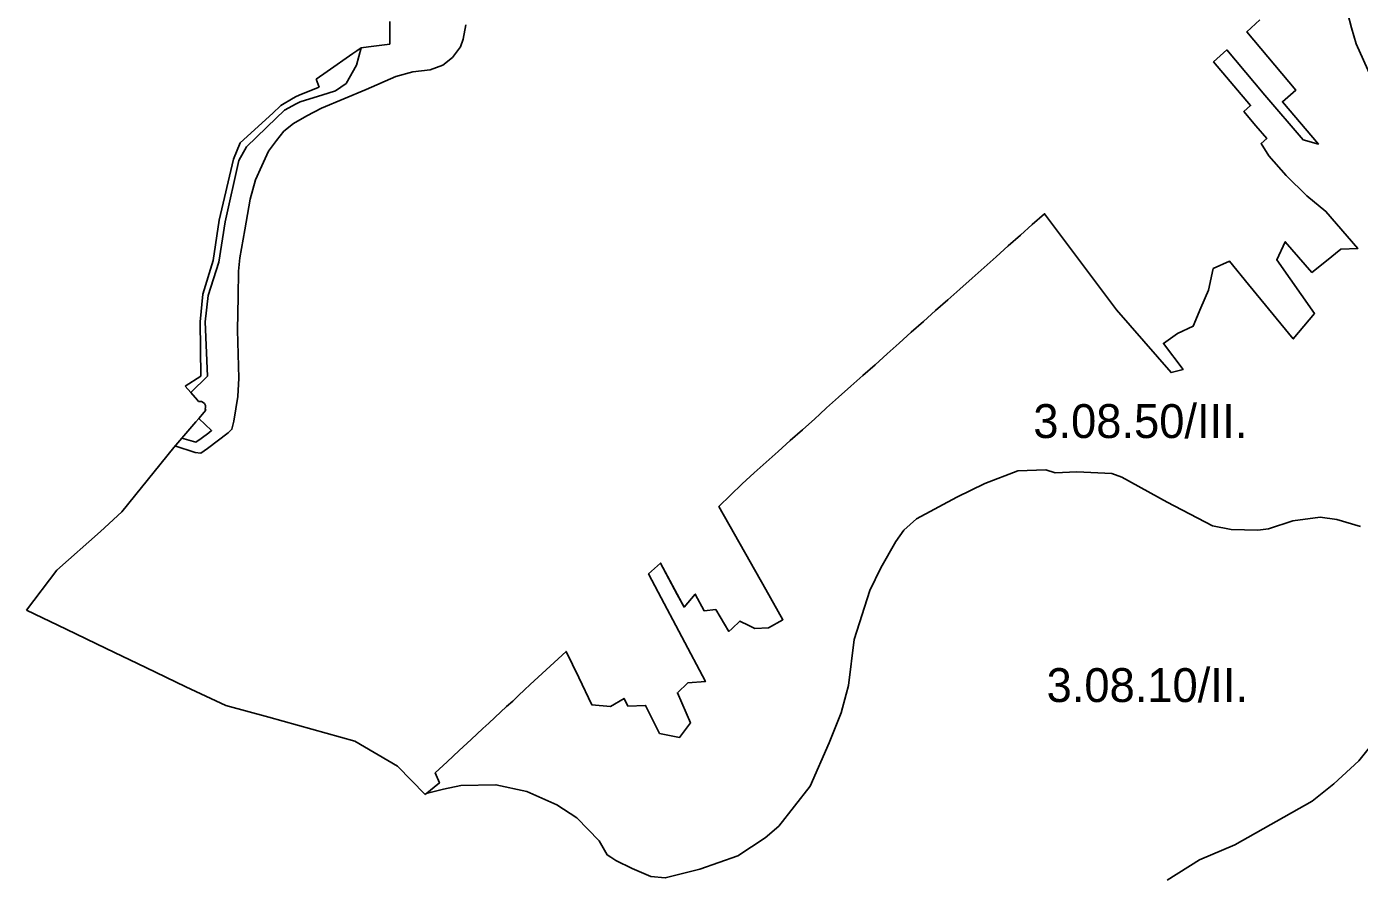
# Model space of a CAD drawing. Extents: x -555509 to -553014, y -1186753 to -1182560.
# Drawn here: x -555343 to -554556, y -1183564 to -1183061 of the extents above; entities that cross this region are included whole.
import ezdxf

# ---------------------------------------------------------------- set-up
doc = ezdxf.new("R2010")
doc.units = 0
for name, color, linetype in [('I_2_Leg_HV', 7, 'Continuous'), ('Level 29', 7, 'Continuous'), ('Level 52', 7, 'Continuous'), ('pěší_tr', 7, 'Continuous'), ('ZM2_KOO_legenda', 7, 'Continuous')]:
    doc.layers.add(name, color=color, linetype=linetype)

msp = doc.modelspace()

# ---------------------------------------------------------------- linework, layer by layer
at = {"layer": 'I_2_Leg_HV'}
for p, q in [((-555150.21, -1183076.55), (-555165.32, -1183087.1)), ((-555147.87, -1183074.92), (-555150.21, -1183076.55)), ((-555147.9, -1183083.4), (-555145.25, -1183073.09)), ((-555145.25, -1183073.09), (-555147.87, -1183074.92)), ((-555154.03, -1183094.28), (-555147.9, -1183083.4)), ((-555165.32, -1183087.1), (-555171.88, -1183091.68)), ((-555171.88, -1183091.68), (-555170.12, -1183096.4)), ((-555180.37, -1183100.59), (-555183.57, -1183101.9)), ((-555170.12, -1183096.4), (-555180.37, -1183100.59)), ((-555178.05, -1183104.03), (-555168.37, -1183101.11)), ((-555168.37, -1183101.11), (-555160.34, -1183098.5)), ((-555160.34, -1183098.5), (-555154.03, -1183094.28)), ((-555192.92, -1183107.44), (-555197.47, -1183111.63)), ((-555192.57, -1183107.12), (-555192.92, -1183107.44)), ((-555185.41, -1183102.97), (-555192.57, -1183107.12)), ((-555190.42, -1183109.88), (-555183.51, -1183106.21)), ((-555183.57, -1183101.9), (-555185.41, -1183102.97)), ((-555183.51, -1183106.21), (-555181.18, -1183104.98)), ((-555181.18, -1183104.98), (-555178.05, -1183104.03)), ((-555197.47, -1183111.63), (-555216.67, -1183129.28)), ((-555213.01, -1183131.64), (-555195.22, -1183114.5)), ((-555195.22, -1183114.5), (-555190.88, -1183110.32)), ((-555190.88, -1183110.32), (-555190.42, -1183109.88)), ((-555216.67, -1183129.28), (-555220.56, -1183138.88)), ((-555217.51, -1183139.66), (-555213.01, -1183131.64)), ((-555220.56, -1183138.88), (-555229.05, -1183174.91)), ((-555225.56, -1183175.8), (-555217.51, -1183139.66)), ((-555229.05, -1183174.91), (-555232.69, -1183198.75)), ((-555229.3, -1183199.63), (-555225.56, -1183175.8)), ((-555232.69, -1183198.75), (-555238.68, -1183218.56)), ((-555235.61, -1183219.26), (-555229.3, -1183199.63)), ((-555238.68, -1183218.56), (-555240.29, -1183234.86)), ((-555237.29, -1183234.87), (-555235.61, -1183219.26)), ((-555240.29, -1183234.86), (-555239.9, -1183266.86)), ((-555235.9, -1183266.88), (-555237.29, -1183234.87)), ((-555239.9, -1183266.86), (-555249.2, -1183272.88)), ((-555245.9, -1183276.62), (-555235.9, -1183266.88)), ((-555249.2, -1183272.88), (-555245.9, -1183276.62)), ((-555246.44, -1183298.03), (-555248.77, -1183300.73)), ((-555242.85, -1183293.87), (-555246.44, -1183298.03)), ((-555241.16, -1183291.91), (-555242.85, -1183293.87)), ((-555233.51, -1183299.01), (-555241.16, -1183291.91)), ((-555248.77, -1183300.73), (-555251.14, -1183303.48)), ((-555251.14, -1183303.48), (-555242.77, -1183305.96)), ((-555242.77, -1183305.96), (-555239.74, -1183303.69)), ((-555239.74, -1183303.69), (-555235.27, -1183300.33)), ((-555235.27, -1183300.33), (-555233.51, -1183299.01))]:
    msp.add_line(p, q, dxfattribs=at)
at = {"layer": 'Level 29'}
for points in [[(-554562.53, -1183053.13), (-554560.35, -1183061.34), (-554557.75, -1183070.88), (-554544.62, -1183099.75)], [(-554614.53, -1183056.65), (-554622.33, -1183063.77), (-554593.26, -1183098.14), (-554601.26, -1183104.98), (-554580.02, -1183129.98), (-554589.05, -1183127.49), (-554611.53, -1183101.05), (-554628.97, -1183080.53), (-554634.15, -1183074.43), (-554638.03, -1183077.94), (-554641.91, -1183081.47), (-554620.03, -1183107.23), (-554624, -1183110.83), (-554616.95, -1183119.13), (-554610.45, -1183126.73), (-554613.79, -1183129.59), (-554609.19, -1183136.97), (-554598.93, -1183148.57), (-554586.83, -1183160.5), (-554575.55, -1183169.73), (-554556.74, -1183191.61), (-554566.7, -1183192.05), (-554575.24, -1183198.88), (-554583.79, -1183205.7), (-554599.54, -1183187.59), (-554604.55, -1183198.21), (-554582.34, -1183229.95), (-554594.82, -1183244.98), (-554621.27, -1183212.77), (-554632.58, -1183199.03), (-554642.11, -1183203.45), (-554644.88, -1183216.26), (-554649.38, -1183226.72), (-554653.85, -1183237.43), (-554663.25, -1183241.85), (-554671.5, -1183247.6), (-554659.9, -1183262.96), (-554667.03, -1183264.88), (-554699.17, -1183227.83), (-554741.66, -1183171.12), (-554748.95, -1183177.43), (-554755.99, -1183183.75), (-554763.1, -1183190.08), (-554770.25, -1183196.43), (-554777.42, -1183202.78), (-554784.53, -1183209.17), (-554791.73, -1183215.56), (-554798.88, -1183221.86), (-554806.02, -1183228.28), (-554813.12, -1183234.65), (-554820.36, -1183241.01), (-554827.49, -1183247.43), (-554834.63, -1183253.83), (-554841.79, -1183260.25), (-554848.95, -1183266.59), (-554852.59, -1183269.75), (-554856.15, -1183272.92), (-554863.29, -1183279.39), (-554870.39, -1183285.71), (-554874.36, -1183289.36), (-554877.44, -1183292.2), (-554884.69, -1183298.58), (-554891.82, -1183304.91), (-554898.92, -1183311.49), (-554906.1, -1183317.74), (-554913.17, -1183324.08), (-554920.26, -1183330.57), (-554927.09, -1183337.26), (-554933.97, -1183343.87), (-554906.3, -1183392.96), (-554896.2, -1183410.77), (-554904.61, -1183415.44), (-554912.81, -1183415.84), (-554916.31, -1183414.13), (-554921.57, -1183411.56), (-554926.22, -1183415.89), (-554928.05, -1183417.59), (-554935.83, -1183404.66), (-554942.63, -1183405.5), (-554947.99, -1183395.55), (-554954.54, -1183403.27), (-554968.43, -1183377.25), (-554975.5, -1183383.63), (-554969.8, -1183394.42), (-554941.94, -1183447.21), (-554952.33, -1183447.96), (-554958.47, -1183453.8), (-554950.83, -1183471.64), (-554957.16, -1183480.2), (-554969.02, -1183477.84), (-554977.32, -1183461.31), (-554987.72, -1183461.68), (-554989.94, -1183457.2), (-554998.08, -1183461.92)], [(-554555.19, -1183355.75), (-554569.19, -1183351.5), (-554578.94, -1183350.25), (-554595.06, -1183352.38), (-554609.5, -1183357), (-554615.81, -1183357.88), (-554631.5, -1183357.5), (-554642.56, -1183355.38), (-554669.25, -1183341.38), (-554696, -1183326.5), (-554701.88, -1183324.38), (-554722.69, -1183323.5), (-554735.38, -1183324), (-554740.94, -1183322.25), (-554757.44, -1183322.75), (-554776.94, -1183330.38), (-554793.5, -1183338.38), (-554817.25, -1183351.12), (-554824.88, -1183357.88), (-554829.5, -1183364.63), (-554838.44, -1183380), (-554844.81, -1183393.5), (-554854.12, -1183422.38), (-554857.5, -1183449.5), (-554858.75, -1183454.63), (-554861.75, -1183465.63), (-554868.94, -1183483.38), (-554880, -1183508.88), (-554898.62, -1183532.62), (-554906.69, -1183539.38), (-554922.81, -1183550), (-554945.25, -1183558), (-554965.62, -1183563.13), (-554974.12, -1183562.25), (-554985.12, -1183557.62), (-554994.88, -1183552.88), (-554997.81, -1183550.88), (-555000, -1183549.5), (-555004.69, -1183541.25), (-555017.81, -1183527.63), (-555029.69, -1183520), (-555047.44, -1183512), (-555065.69, -1183508.12), (-555086.44, -1183508.62), (-555096.62, -1183510.75), (-555106.92, -1183513.36)], [(-554998.08, -1183461.92), (-555008.94, -1183460.95), (-555016.79, -1183444.75), (-555024.25, -1183429.37), (-555031.27, -1183435.88), (-555038.3, -1183442.38), (-555045.38, -1183448.95), (-555048.86, -1183452.17), (-555052.35, -1183455.43), (-555055.75, -1183458.74), (-555059.32, -1183461.97), (-555066.31, -1183468.45), (-555069.87, -1183471.69), (-555073.35, -1183474.96), (-555080.36, -1183481.47), (-555087.4, -1183487.96), (-555094.43, -1183494.49), (-555101.51, -1183500.99), (-555099.02, -1183506.99), (-555107.46, -1183513.79)], [(-554541.19, -1183475.38), (-554556.06, -1183494), (-554570.88, -1183507.5), (-554583.62, -1183517.75), (-554629.38, -1183543.63), (-554650.19, -1183552.5), (-554669.25, -1183564.38)]]:
    msp.add_lwpolyline(points, dxfattribs=at)
at = {"layer": 'Level 52'}
msp.add_lwpolyline([(-555246.44, -1183298.03), (-555248.77, -1183300.73), (-555251.14, -1183303.48), (-555242.77, -1183305.96), (-555239.74, -1183303.69), (-555235.27, -1183300.33), (-555233.51, -1183299.01), (-555241.16, -1183291.91), (-555242.85, -1183293.87), (-555246.44, -1183298.03)], dxfattribs=at)
at = {"layer": 'pěší_tr'}
msp.add_lwpolyline([(-555255.16, -1183308.13), (-555243.18, -1183312.02), (-555239.89, -1183312.36), (-555235.92, -1183309.55), (-555223.73, -1183300.37), (-555221.53, -1183298.25), (-555220.51, -1183293.52), (-555218.04, -1183278.99), (-555217.42, -1183268.17), (-555218.24, -1183239.88), (-555217.9, -1183219.87), (-555217.7, -1183205.07), (-555216.88, -1183197.12), (-555213.86, -1183180.68), (-555210.71, -1183162.39), (-555207.56, -1183151.09), (-555203.93, -1183142.73), (-555200.02, -1183134.23), (-555195.23, -1183127.86), (-555190.84, -1183122.38), (-555185.09, -1183117.86), (-555177.34, -1183113.27), (-555168.71, -1183108.75), (-555142.2, -1183097.79), (-555124.73, -1183090.18), (-555114.8, -1183087.37), (-555104.45, -1183086.14), (-555096.91, -1183083.4), (-555091.3, -1183078.88), (-555086.64, -1183072.64), (-555085.06, -1183068.12), (-555083.35, -1183059.56)], dxfattribs=at)
at = {"layer": 'ZM2_KOO_legenda'}
for p, q in [((-555128.37, -1183057.57), (-555128.31, -1183071)), ((-554622.33, -1183063.77), (-554614.53, -1183056.65)), ((-554593.26, -1183098.14), (-554622.33, -1183063.77)), ((-555145.25, -1183073.09), (-555147.9, -1183083.4)), ((-555140.92, -1183072.56), (-555145.25, -1183073.09)), ((-555128.31, -1183071), (-555140.92, -1183072.56)), ((-554641.91, -1183081.47), (-554638.03, -1183077.94)), ((-554638.03, -1183077.94), (-554634.15, -1183074.43)), ((-554634.15, -1183074.43), (-554628.97, -1183080.53)), ((-555147.9, -1183083.4), (-555154.03, -1183094.28)), ((-554620.03, -1183107.23), (-554641.91, -1183081.47)), ((-554628.97, -1183080.53), (-554611.53, -1183101.05)), ((-555168.37, -1183101.11), (-555178.05, -1183104.03)), ((-555160.34, -1183098.5), (-555168.37, -1183101.11)), ((-555154.03, -1183094.28), (-555160.34, -1183098.5)), ((-554611.53, -1183101.05), (-554589.05, -1183127.49)), ((-554601.26, -1183104.98), (-554593.26, -1183098.14)), ((-555183.51, -1183106.21), (-555190.42, -1183109.88)), ((-555181.18, -1183104.98), (-555183.51, -1183106.21)), ((-555178.05, -1183104.03), (-555181.18, -1183104.98)), ((-554624, -1183110.83), (-554620.03, -1183107.23)), ((-554580.02, -1183129.98), (-554601.26, -1183104.98)), ((-555195.22, -1183114.5), (-555213.01, -1183131.64)), ((-555190.88, -1183110.32), (-555195.22, -1183114.5)), ((-555190.42, -1183109.88), (-555190.88, -1183110.32)), ((-554616.95, -1183119.13), (-554624, -1183110.83)), ((-554610.45, -1183126.73), (-554616.95, -1183119.13)), ((-555213.01, -1183131.64), (-555217.51, -1183139.66)), ((-554613.79, -1183129.59), (-554610.45, -1183126.73)), ((-554609.19, -1183136.97), (-554613.79, -1183129.59)), ((-554589.05, -1183127.49), (-554580.02, -1183129.98)), ((-555217.51, -1183139.66), (-555225.56, -1183175.8)), ((-554598.93, -1183148.57), (-554609.19, -1183136.97)), ((-554586.83, -1183160.5), (-554598.93, -1183148.57)), ((-554575.55, -1183169.73), (-554586.83, -1183160.5)), ((-554748.95, -1183177.43), (-554741.66, -1183171.12)), ((-554741.66, -1183171.12), (-554699.17, -1183227.83)), ((-554556.74, -1183191.61), (-554575.55, -1183169.73)), ((-555225.56, -1183175.8), (-555229.3, -1183199.63)), ((-554755.99, -1183183.75), (-554748.95, -1183177.43)), ((-554763.1, -1183190.08), (-554755.99, -1183183.75)), ((-554604.55, -1183198.21), (-554599.54, -1183187.59)), ((-554599.54, -1183187.59), (-554583.79, -1183205.7)), ((-554770.25, -1183196.43), (-554763.1, -1183190.08)), ((-554575.24, -1183198.88), (-554566.7, -1183192.05)), ((-554566.7, -1183192.05), (-554556.74, -1183191.61)), ((-555229.3, -1183199.63), (-555235.61, -1183219.26)), ((-554784.53, -1183209.17), (-554777.42, -1183202.78)), ((-554777.42, -1183202.78), (-554770.25, -1183196.43)), ((-554644.88, -1183216.26), (-554642.11, -1183203.45)), ((-554642.11, -1183203.45), (-554632.58, -1183199.03)), ((-554632.58, -1183199.03), (-554621.27, -1183212.77)), ((-554582.34, -1183229.95), (-554604.55, -1183198.21)), ((-554583.79, -1183205.7), (-554575.24, -1183198.88)), ((-554791.73, -1183215.56), (-554784.53, -1183209.17)), ((-555235.61, -1183219.26), (-555237.29, -1183234.87)), ((-554798.88, -1183221.86), (-554791.73, -1183215.56)), ((-554649.38, -1183226.72), (-554644.88, -1183216.26)), ((-554621.27, -1183212.77), (-554594.82, -1183244.98)), ((-554806.02, -1183228.28), (-554798.88, -1183221.86)), ((-554653.85, -1183237.43), (-554649.38, -1183226.72)), ((-555237.29, -1183234.87), (-555235.9, -1183266.88)), ((-554820.36, -1183241.01), (-554813.12, -1183234.65)), ((-554813.12, -1183234.65), (-554806.02, -1183228.28)), ((-554699.17, -1183227.83), (-554667.03, -1183264.88)), ((-554594.82, -1183244.98), (-554582.34, -1183229.95)), ((-554827.49, -1183247.43), (-554820.36, -1183241.01)), ((-554671.5, -1183247.6), (-554663.25, -1183241.85)), ((-554663.25, -1183241.85), (-554653.85, -1183237.43)), ((-554834.63, -1183253.83), (-554827.49, -1183247.43)), ((-554659.9, -1183262.96), (-554671.5, -1183247.6)), ((-554841.79, -1183260.25), (-554834.63, -1183253.83)), ((-555235.9, -1183266.88), (-555245.9, -1183276.62)), ((-554852.59, -1183269.75), (-554848.95, -1183266.59)), ((-554848.95, -1183266.59), (-554841.79, -1183260.25)), ((-554667.03, -1183264.88), (-554659.9, -1183262.96)), ((-554863.29, -1183279.39), (-554856.15, -1183272.92)), ((-554856.15, -1183272.92), (-554852.59, -1183269.75)), ((-555245.9, -1183276.62), (-555241.95, -1183281.12)), ((-555241.95, -1183281.12), (-555241.21, -1183281.96)), ((-555241.21, -1183281.96), (-555240.82, -1183281.86)), ((-555240.82, -1183281.86), (-555240.47, -1183281.86)), ((-555240.47, -1183281.86), (-555239.42, -1183281.93)), ((-555239.42, -1183281.93), (-555238.48, -1183282.43)), ((-555238.48, -1183282.43), (-555237.69, -1183283.17)), ((-554870.39, -1183285.71), (-554863.29, -1183279.39)), ((-555236.88, -1183286.96), (-555241.16, -1183291.91)), ((-555237.69, -1183283.17), (-555237.14, -1183284.24)), ((-555237.09, -1183285.5), (-555237.28, -1183286.49)), ((-555237.28, -1183286.49), (-555236.88, -1183286.96)), ((-555237.14, -1183284.24), (-555237.09, -1183285.5)), ((-554877.44, -1183292.2), (-554874.36, -1183289.36)), ((-554874.36, -1183289.36), (-554870.39, -1183285.71)), ((-555241.16, -1183291.91), (-555233.51, -1183299.01)), ((-554884.69, -1183298.58), (-554877.44, -1183292.2)), ((-555251.14, -1183303.48), (-555255.88, -1183308.96)), ((-555242.77, -1183305.96), (-555251.14, -1183303.48)), ((-555239.74, -1183303.69), (-555242.77, -1183305.96)), ((-555235.27, -1183300.33), (-555239.74, -1183303.69)), ((-555233.51, -1183299.01), (-555235.27, -1183300.33)), ((-554898.92, -1183311.49), (-554891.82, -1183304.91)), ((-554891.82, -1183304.91), (-554884.69, -1183298.58)), ((-555255.88, -1183308.96), (-555286.46, -1183347.02)), ((-554906.1, -1183317.74), (-554898.92, -1183311.49)), ((-554913.17, -1183324.08), (-554906.1, -1183317.74)), ((-554920.26, -1183330.57), (-554913.17, -1183324.08)), ((-554933.97, -1183343.87), (-554927.09, -1183337.26)), ((-554927.09, -1183337.26), (-554920.26, -1183330.57)), ((-554906.3, -1183392.96), (-554933.97, -1183343.87)), ((-555286.46, -1183347.02), (-555299.11, -1183358.62)), ((-555299.11, -1183358.62), (-555324.88, -1183381.52)), ((-555324.88, -1183381.52), (-555342.75, -1183405.14)), ((-554975.5, -1183383.63), (-554968.43, -1183377.25)), ((-554969.8, -1183394.42), (-554975.5, -1183383.63)), ((-554968.43, -1183377.25), (-554958.54, -1183395.77)), ((-554941.94, -1183447.21), (-554969.8, -1183394.42)), ((-554958.54, -1183395.77), (-554954.54, -1183403.27)), ((-554954.54, -1183403.27), (-554947.99, -1183395.55)), ((-554947.99, -1183395.55), (-554942.63, -1183405.5)), ((-554896.2, -1183410.77), (-554906.3, -1183392.96)), ((-555342.75, -1183405.14), (-555319.32, -1183416.36)), ((-554942.63, -1183405.5), (-554935.83, -1183404.66)), ((-554935.83, -1183404.66), (-554928.05, -1183417.59)), ((-555319.32, -1183416.36), (-555295.77, -1183427.64)), ((-554928.05, -1183417.59), (-554926.22, -1183415.89)), ((-554926.22, -1183415.89), (-554921.57, -1183411.56)), ((-554921.57, -1183411.56), (-554916.31, -1183414.13)), ((-554916.31, -1183414.13), (-554912.81, -1183415.84)), ((-554912.81, -1183415.84), (-554904.61, -1183415.44)), ((-554904.61, -1183415.44), (-554896.2, -1183410.77)), ((-555295.77, -1183427.64), (-555272.32, -1183438.88)), ((-555031.27, -1183435.88), (-555024.25, -1183429.37)), ((-555024.25, -1183429.37), (-555016.79, -1183444.75)), ((-555272.32, -1183438.88), (-555248.68, -1183450.24)), ((-555038.3, -1183442.38), (-555031.27, -1183435.88)), ((-555045.38, -1183448.95), (-555038.3, -1183442.38)), ((-555016.79, -1183444.75), (-555008.94, -1183460.95)), ((-554952.33, -1183447.96), (-554941.94, -1183447.21)), ((-555248.68, -1183450.24), (-555225.23, -1183461.43)), ((-555055.75, -1183458.74), (-555052.35, -1183455.43)), ((-555052.35, -1183455.43), (-555048.86, -1183452.17)), ((-555048.86, -1183452.17), (-555045.38, -1183448.95)), ((-554958.47, -1183453.8), (-554952.33, -1183447.96)), ((-554950.83, -1183471.64), (-554958.47, -1183453.8)), ((-555225.23, -1183461.43), (-555199.76, -1183468.31)), ((-555066.31, -1183468.45), (-555059.32, -1183461.97)), ((-555059.32, -1183461.97), (-555055.75, -1183458.74)), ((-555008.94, -1183460.95), (-554998.08, -1183461.92)), ((-554998.08, -1183461.92), (-554989.94, -1183457.2)), ((-554989.94, -1183457.2), (-554987.72, -1183461.68)), ((-554987.72, -1183461.68), (-554977.32, -1183461.31)), ((-554977.32, -1183461.31), (-554969.02, -1183477.84)), ((-555199.76, -1183468.31), (-555174.33, -1183475.35)), ((-555069.87, -1183471.69), (-555066.31, -1183468.45)), ((-555174.33, -1183475.35), (-555148.99, -1183482.44)), ((-555080.36, -1183481.47), (-555073.35, -1183474.96)), ((-555073.35, -1183474.96), (-555069.87, -1183471.69)), ((-554969.02, -1183477.84), (-554957.16, -1183480.2)), ((-554957.16, -1183480.2), (-554950.83, -1183471.64)), ((-555148.99, -1183482.44), (-555123.73, -1183497.05)), ((-555087.4, -1183487.96), (-555080.36, -1183481.47)), ((-555101.51, -1183500.99), (-555094.43, -1183494.49)), ((-555094.43, -1183494.49), (-555087.4, -1183487.96)), ((-555123.73, -1183497.05), (-555107.46, -1183513.79)), ((-555099.02, -1183506.99), (-555101.51, -1183500.99)), ((-555107.46, -1183513.79), (-555099.02, -1183506.99))]:
    msp.add_line(p, q, dxfattribs=at)

# ---------------------------------------------------------------- texts
at = {"layer": 'Level 29'}
for s, p in [('3.08.50/III.', (-554748.33, -1183303.47)), ('3.08.10/II.', (-554740.49, -1183459.29))]:
    msp.add_text(s, height=20, dxfattribs=at).set_placement(p)

doc.saveas('drawing.dxf')
